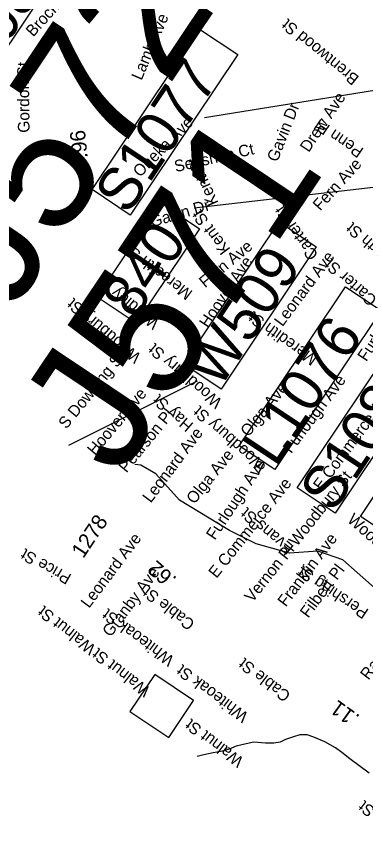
# Model space of a CAD drawing. Extents: x 1716282 to 1717158, y 799307 to 801078.
# Drawn here: x 1716566.1 to 1716607.4, y 799385.8 to 799484.2 of the extents above; entities that cross this region are included whole.
import ezdxf

# ---------------------------------------------------------------- set-up
doc = ezdxf.new("R2010")
doc.units = 0
for name, color, linetype in [('Exist Hydrographic Misc Water Feature', 7, 'Continuous'), ('Exist Road Non-System Structure Non-Sys Other Number Label', 7, 'Continuous'), ('Exist Road Non-System Type 51 Label', 7, 'Continuous'), ('Exist Road Primary Interstate Structure Cantilever Sign Number Label', 7, 'Continuous'), ('Exist Road Primary US Structure Ovrhead Sign CELL', 7, 'Continuous'), ('Exist Road Primary US Structure Standard Bridge Number Label', 7, 'Continuous'), ('Exist Road Secondary Mileage Hundredths English Label', 7, 'Continuous'), ('Exist Road Secondary Mileage Tenths English Label', 7, 'Continuous'), ('Exist Road Secondary Structure NCDOT Private Pedestrian Number Label', 7, 'Continuous'), ('Exist Road Secondary Structure Standard Bridge Number Label', 7, 'Continuous'), ('Exist Road Secondary Type 51 Number Label', 7, 'Continuous')]:
    doc.layers.add(name, color=color, linetype=linetype)

msp = doc.modelspace()

# ---------------------------------------------------------------- linework, layer by layer
at = {"layer": 'Exist Hydrographic Misc Water Feature'}
for points in [[(1716634.283, 799412.094), (1716631.001, 799413.172), (1716629.589, 799413.174), (1716628.557, 799412.863), (1716626.769, 799411.704), (1716621.009, 799409.256), (1716620.1, 799409.217), (1716619.381, 799409.463), (1716618.622, 799409.912), (1716616.792, 799411.137), (1716609.838, 799415.261), (1716604.726, 799419.771), (1716601.769, 799420.773), (1716598.43, 799420.566), (1716594.486, 799421.653), (1716591.302, 799423.243), (1716585.392, 799426.833), (1716582.572, 799429.941), (1716580.814, 799430.996), (1716580.091, 799431.043)], [(1716607.844, 799394.457), (1716605.562, 799396.154), (1716604.605, 799396.915), (1716603.871, 799397.485), (1716602.592, 799398.184), (1716601.318, 799398.737), (1716600.517, 799399.005), (1716599.64, 799399.005), (1716598.889, 799398.782), (1716597.951, 799398.436), (1716597.32, 799398.13), (1716596.572, 799398.011), (1716595.59, 799398.013), (1716594.208, 799398.151), (1716593.264, 799397.951), (1716592.11, 799397.65), (1716591.276, 799397.305), (1716590.486, 799397.073), (1716589.358, 799396.861), (1716588.269, 799396.656), (1716587.481, 799396.437)]]:
    msp.add_lwpolyline(points, dxfattribs=at)
at = {"layer": 'Exist Road Primary Interstate Structure Cantilever Sign Number Label'}
msp.add_lwpolyline([(1716592.464, 799433.288), (1716605.07, 799452.122), (1716609.274, 799449.308), (1716596.669, 799430.474)], close=True, dxfattribs=at)
at = {"layer": 'Exist Road Primary US Structure Ovrhead Sign CELL'}
msp.add_line((1716622.988, 799477.746), (1716588.366, 799472.147), dxfattribs=at)
for points in [[(1716556.007, 799476.96), (1716568.75, 799495.999), (1716573.259, 799492.981), (1716560.516, 799473.942)], [(1716575.03, 799463.651), (1716587.773, 799482.69), (1716592.282, 799479.672), (1716579.539, 799460.633)], [(1716599.331, 799428.313), (1716612.075, 799447.352), (1716616.583, 799444.335), (1716603.84, 799425.296)]]:
    msp.add_lwpolyline(points, close=True, dxfattribs=at)
at = {"layer": 'Exist Road Primary US Structure Standard Bridge Number Label'}
msp.add_line((1716579.51, 799401.773), (1716584.117, 799398.689), dxfattribs=at)
msp.add_lwpolyline([(1716606.841, 799424.91), (1716614.333, 799436.105), (1716618.962, 799433.007), (1716611.469, 799421.813)], close=True, dxfattribs=at)
msp.add_lwpolyline([(1716584.117, 799398.689), (1716587.063, 799403.092), (1716582.456, 799406.175), (1716579.51, 799401.773)], dxfattribs=at)
at = {"layer": 'Exist Road Secondary Structure NCDOT Private Pedestrian Number Label'}
msp.add_line((1716572.282, 799433.348), (1716587.519, 799440.988), dxfattribs=at)
msp.add_lwpolyline([(1716585.904, 799442.956), (1716597.192, 799459.821), (1716601.594, 799456.876), (1716590.305, 799440.01)], close=True, dxfattribs=at)
at = {"layer": 'Exist Road Secondary Structure Standard Bridge Number Label'}
msp.add_line((1716637.023, 799467.254), (1716587.112, 799461.446), dxfattribs=at)
msp.add_lwpolyline([(1716575.627, 799450.914), (1716583.119, 799462.108), (1716587.747, 799459.01), (1716580.255, 799447.816)], close=True, dxfattribs=at)

# ---------------------------------------------------------------- texts
at = {"layer": 'Exist Road Non-System Structure Non-Sys Other Number Label'}
for s, p in [('J572', (1716565.359, 799448.751)), ('J571', (1716578.172, 799429.263))]:
    msp.add_text(s, height=15.223, rotation=56.20506, dxfattribs=at).set_placement(p)
at = {"layer": 'Exist Road Non-System Type 51 Label'}
for s, rotation, p in [('Brockett Ave', 47.72572, (1716568.048, 799481.69)), ('Lamb Ave', 66.98068, (1716580.885, 799476.534)), ('Brentwood St', 140.73082, (1716606.759, 799476.989)), ('Gordon St', 90.65456, (1716567.626, 799470.403)), ('Drew Ave', 56.20506, (1716600.693, 799467.989)), ('Gavin Dr', 68.4875, (1716596.973, 799466.845)), ('Oneka Ave', 45.14691, (1716580.698, 799465.045)), ('Penn Pl', 145.78189, (1716607.305, 799468.467)), ('Seashire Ct', 12.95045, (1716584.939, 799465.715)), ('Kent Ct', 114.21451, (1716590.032, 799462.088)), ('Fern Ave', 47.84232, (1716602.05, 799461.061)), ('Gavin Dr', 16.44705, (1716582.129, 799459.183)), ('Kent St', 126.75616, (1716591.466, 799456.585)), ('Carter St', 124.82173, (1716601.892, 799455.892)), ('Worth St', 139.15735, (1716611.286, 799455.197)), ('Meredith St', 142.68794, (1716587.04, 799451.554)), ('Fern Ave', 39.71241, (1716588.416, 799451.946)), ('Leonard Ave', 53.17725, (1716597.579, 799447.326)), ('Hoover Ave', 56.20506, (1716588.761, 799447.157)), ('Carter St', 139.04889, (1716608.876, 799450.747)), ('Windley St', 140.82385, (1716583.103, 799448.042)), ('Furlough Ave', 56.20506, (1716607.511, 799443.186)), ('Woodbury St', 139.72682, (1716580.935, 799443.996)), ('Meredith St', 144.3878, (1716601.827, 799443.8)), ('Woodbury St', 139.62687, (1716590.546, 799438.627)), ('S Downing St', 50.585, (1716571.972, 799435.193)), ('Furlough Ave', 53.27718, (1716598.616, 799432.28)), ('Olga Ave', 50.77207, (1716593.538, 799434.255)), ('Hoover Ave', 49.8338, (1716575.377, 799432.051)), ('E Commerce Ave', 53.35666, (1716602.205, 799427.873)), ('Hay St', 138.97226, (1716587.128, 799435.86)), ('Pearson Pl', 50.72362, (1716579.102, 799429.994)), ('Woodbury St', 138.73775, (1716595.777, 799431.085)), ('Leonard Ave', 53.17725, (1716581.979, 799426.422)), ('Olga Ave', 50.99044, (1716587.136, 799426.278)), ('Furlough Ave', 56.20506, (1716589.577, 799422.02)), ('Woodbury St', 51.71976, (1716599.301, 799421.274)), ('E Commerce Ave', 51.54903, (1716589.77, 799417.493)), ('Evans St', 140.09305, (1716599.02, 799421.325)), ('Woodbury St', 318.71347, (1716605.164, 799424.347)), ('Leonard Ave', 53.02328, (1716574.665, 799413.941)), ('Franklin Ave', 52.9182, (1716597.979, 799414.1)), ('Price St', 150.38757, (1716572.696, 799417.963)), ('Vernon Pl', 51.28804, (1716594.018, 799414.629)), ('Pershing St', 146.20506, (1716607.897, 799413.807)), ('Filbert Pl', 52.86178, (1716600.632, 799412.773)), ('Granby Ave', 52.7865, (1716577.22, 799410.516)), ('Cable St', 142.27585, (1716587.305, 799412.368)), ('Walnut St', 141.74186, (1716575.575, 799409.448)), ('Whiteoak St', 143.50445, (1716584.867, 799408.141)), ('Ragan Ave', 52.34822, (1716607.762, 799405.426)), ('Walnut St', 142.22258, (1716582.041, 799404.485)), ('Cable St', 142.20453, (1716598.657, 799403.883)), ('Whiteoak St', 143.15088, (1716593.647, 799401.46)), ('Walnut St', 142.70957, (1716593.088, 799396.141)), ('Asheboro St', 142.24786, (1716615.288, 799385.094))]:
    msp.add_text(s, height=1.3775, rotation=rotation, dxfattribs=at).set_placement(p)
at = {"layer": 'Exist Road Primary Interstate Structure Cantilever Sign Number Label'}
msp.add_text('L1076', height=5.075, rotation=56.20506, dxfattribs=at).set_placement((1716596.745, 799430.642))
at = {"layer": 'Exist Road Primary US Structure Ovrhead Sign CELL'}
for s, p in [('S1088', (1716560.246, 799473.842)), ('S1077', (1716579.269, 799460.533)), ('S1089', (1716603.57, 799425.196))]:
    msp.add_text(s, height=5.075, rotation=56.20506, dxfattribs=at).set_placement(p)
at = {"layer": 'Exist Road Secondary Mileage Hundredths English Label'}
msp.add_text('.96', height=1.8125, rotation=95.94904, dxfattribs=at).set_placement((1716574.517, 799467.439))
at = {"layer": 'Exist Road Secondary Mileage Tenths English Label'}
for s, rotation, p in [('.62', 138.47646, (1716585.161, 799417.573)), ('.11', 144.16899, (1716606.853, 799401.243))]:
    msp.add_text(s, height=1.8125, rotation=rotation, dxfattribs=at).set_placement(p)
at = {"layer": 'Exist Road Secondary Structure NCDOT Private Pedestrian Number Label'}
msp.add_text('W509', height=5.075, rotation=56.20506, dxfattribs=at).set_placement((1716590.093, 799439.91))
at = {"layer": 'Exist Road Secondary Structure Standard Bridge Number Label'}
msp.add_text('840', height=5.075, rotation=56.20506, dxfattribs=at).set_placement((1716580.118, 799448.126))
at = {"layer": 'Exist Road Secondary Type 51 Number Label'}
msp.add_text('1278', height=1.8125, rotation=56.20506, dxfattribs=at).set_placement((1716573.974, 799419.838))

doc.saveas('drawing.dxf')
